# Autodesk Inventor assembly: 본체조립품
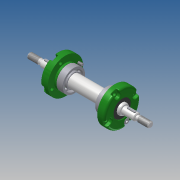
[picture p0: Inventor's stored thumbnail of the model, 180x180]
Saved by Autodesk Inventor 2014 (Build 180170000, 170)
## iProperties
Created: 2015-11
Part Number: 본체조립품
Document SubType Name: Assembly
Designer: Owner
Author: Owner
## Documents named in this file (8)
- C:\Documents and Settings\Owner\바탕 화면\451109V1014\본체조립품.iam
- C:\Documents and Settings\Owner\바탕 화면\451109V1014\본체.ipt
- C:\Documents and Settings\Owner\바탕 화면\451109V1014\커버.ipt
- C:\Documents and Settings\Owner\바탕 화면\451109V1014\베어링 15 x 32 x 9.ipt
- C:\Documents and Settings\Owner\바탕 화면\451109V1014\오일 실 15 25 7.ipt
- C:\Documents and Settings\Owner\바탕 화면\451109V1014\볼트 M4 x 12.ipt
- C:\Documents and Settings\Owner\바탕 화면\451109V1014\축.ipt
- C:\Documents and Settings\Owner\바탕 화면\451109V1014\키 3 x 3 x 12.ipt
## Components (4 placed, 2 different names)
1. KS B 2023 6002 - 15 x 32 x 9:1
2. KS B 2023 6002 - 15 x 32 x 9:2
3. ISO 4762 M4 x 12:1
4. ISO 4762 M4 x 12:2
